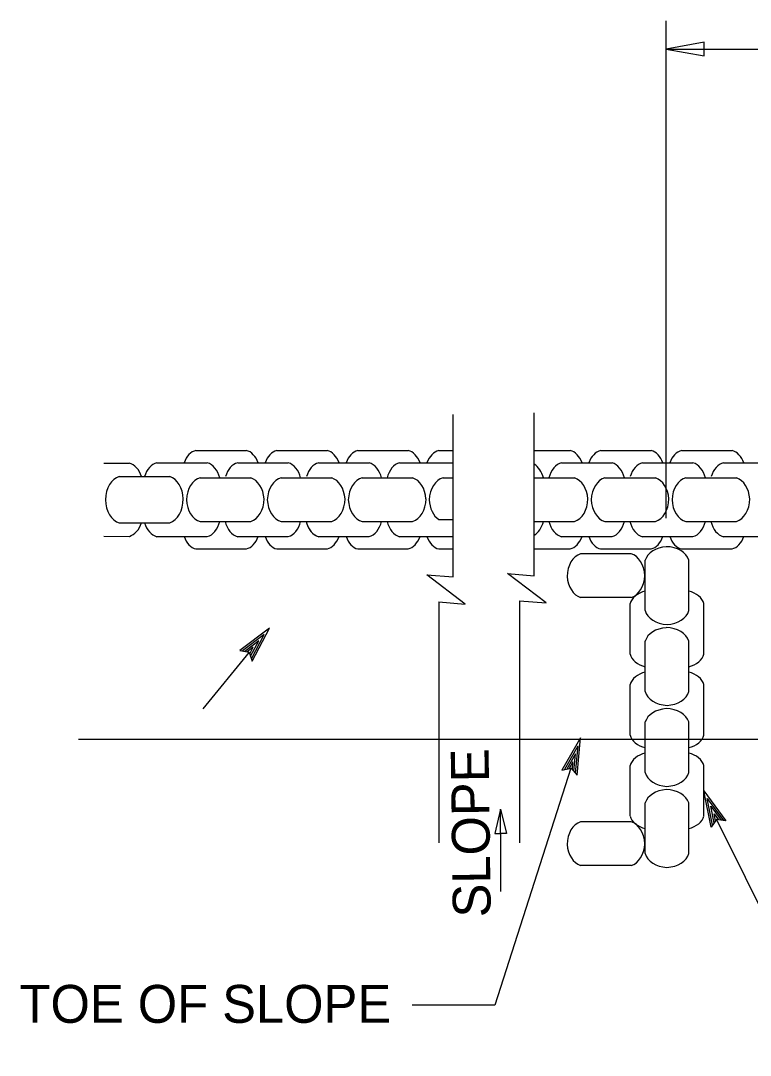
# Model space of a CAD drawing. Extents: x 6707406 to 6714471, y 1868570 to 1872341.
# Drawn here: x 6712391.8 to 6712507.4, y 1870300.6 to 1870464.4 of the extents above; entities that cross this region are included whole.
import ezdxf

# ---------------------------------------------------------------- set-up
doc = ezdxf.new("R2010")
doc.units = 0
for name, color, linetype in [('56 Stg 3 Anno', 7, 'Continuous'), ('C - SANDBAG', 7, 'Continuous'), ('Default', 7, 'Continuous'), ('G-SYMB', 7, 'Continuous'), ('G-TEXT', 7, 'Continuous')]:
    doc.layers.add(name, color=color, linetype=linetype)

# ---------------------------------------------------------------- blocks, each defined once
blk = doc.blocks.new('ARROW')
at = {"layer": 'Default'}
blk.add_lwpolyline([(-0.01042, -0.00183), (0, 0), (-0.01042, 0.00183)], close=True, dxfattribs=at)

msp = doc.modelspace()

# ---------------------------------------------------------------- linework, layer by layer
at = {"layer": '56 Stg 3 Anno'}
for p, q in [((6712431.26, 1870368.21), (6712426.55, 1870364.65)), ((6712428.5, 1870362.99), (6712431.26, 1870368.21)), ((6712431.26, 1870368.21), (6712431.26, 1870368.21)), ((6712430.39, 1870367.19), (6712426.96, 1870364.6)), ((6712428.37, 1870363.37), (6712430.4, 1870367.2)), ((6712426.55, 1870364.65), (6712426.55, 1870364.65)), ((6712426.55, 1870364.65), (6712428.02, 1870364.41)), ((6712429.54, 1870366.19), (6712427.32, 1870364.51)), ((6712428.68, 1870365.18), (6712427.73, 1870364.46)), ((6712428.11, 1870364.11), (6712428.68, 1870365.18)), ((6712428.26, 1870363.76), (6712429.54, 1870366.19)), ((6712428.02, 1870364.41), (6712428.5, 1870362.99)), ((6712428.5, 1870362.99), (6712428.5, 1870362.99)), ((6712480.51, 1870350.81), (6712477.55, 1870345.7)), ((6712480, 1870344.93), (6712480.51, 1870350.81)), ((6712480.51, 1870350.81), (6712480.51, 1870350.81)), ((6712480.1, 1870349.54), (6712477.95, 1870345.82)), ((6712479.71, 1870348.28), (6712478.32, 1870345.88)), ((6712479.47, 1870345.55), (6712479.71, 1870348.28)), ((6712479.73, 1870345.23), (6712480.11, 1870349.55)), ((6712479.31, 1870347.02), (6712478.71, 1870345.99)), ((6712479.21, 1870345.81), (6712479.31, 1870347.02)), ((6712477.55, 1870345.71), (6712479, 1870346.05)), ((6712477.55, 1870345.71), (6712477.55, 1870345.71)), ((6712479, 1870346.05), (6712480, 1870344.93)), ((6712480, 1870344.93), (6712480, 1870344.93)), ((6712501.2, 1870336.67), (6712500.05, 1870342.46)), ((6712500.05, 1870342.46), (6712500.05, 1870342.46)), ((6712500.05, 1870342.46), (6712503.54, 1870337.7)), ((6712501.42, 1870337), (6712500.58, 1870341.25)), ((6712500.59, 1870341.24), (6712503.14, 1870337.77)), ((6712501.65, 1870337.34), (6712501.12, 1870340.03)), ((6712501.12, 1870340.03), (6712502.76, 1870337.79)), ((6712501.89, 1870337.63), (6712501.65, 1870338.82)), ((6712501.65, 1870338.82), (6712502.36, 1870337.86)), ((6712502.06, 1870337.89), (6712501.2, 1870336.67)), ((6712503.54, 1870337.7), (6712502.06, 1870337.89)), ((6712503.54, 1870337.7), (6712503.54, 1870337.7)), ((6712501.2, 1870336.67), (6712501.2, 1870336.67))]:
    msp.add_line(p, q, dxfattribs=at)
at = {"layer": 'C - SANDBAG'}
for p, q in [((6712419.58, 1870396.35), (6712427.59, 1870396.35)), ((6712432.4, 1870396.35), (6712440.41, 1870396.35)), ((6712445.22, 1870396.35), (6712453.23, 1870396.35)), ((6712445.22, 1870396.35), (6712453.23, 1870396.35)), ((6712458.04, 1870396.35), (6712460.36, 1870396.35)), ((6712473.18, 1870396.35), (6712478.87, 1870396.35)), ((6712483.68, 1870396.35), (6712491.69, 1870396.35)), ((6712496.51, 1870396.35), (6712504.51, 1870396.35)), ((6712405, 1870394.34), (6712409.05, 1870394.35)), ((6712413.39, 1870394.4), (6712421.39, 1870394.4)), ((6712426.21, 1870394.39), (6712434.22, 1870394.39)), ((6712439.03, 1870394.39), (6712447.04, 1870394.39)), ((6712439.03, 1870394.39), (6712447.04, 1870394.39)), ((6712451.85, 1870394.39), (6712460.36, 1870394.39)), ((6712477.49, 1870394.39), (6712485.5, 1870394.39)), ((6712490.31, 1870394.39), (6712498.32, 1870394.39)), ((6712503.13, 1870394.39), (6712511.14, 1870394.39)), ((6712407.45, 1870392.19), (6712415.46, 1870392.19)), ((6712420.27, 1870391.99), (6712428.28, 1870391.99)), ((6712433.09, 1870391.99), (6712441.1, 1870391.99)), ((6712445.91, 1870391.99), (6712453.92, 1870391.99)), ((6712445.91, 1870391.99), (6712453.92, 1870391.99)), ((6712458.73, 1870391.99), (6712460.36, 1870391.99)), ((6712473.18, 1870391.99), (6712479.56, 1870391.99)), ((6712484.37, 1870391.99), (6712492.38, 1870391.99)), ((6712497.19, 1870391.99), (6712505.2, 1870391.99)), ((6712407.45, 1870384.89), (6712415.46, 1870384.89)), ((6712420.27, 1870385.1), (6712428.28, 1870385.1)), ((6712433.09, 1870385.1), (6712441.1, 1870385.1)), ((6712445.91, 1870385.1), (6712453.92, 1870385.1)), ((6712445.91, 1870385.1), (6712453.92, 1870385.1)), ((6712458.04, 1870385.41), (6712460.36, 1870385.41)), ((6712473.18, 1870385.1), (6712479.56, 1870385.1)), ((6712484.37, 1870385.1), (6712492.38, 1870385.1)), ((6712497.19, 1870385.1), (6712505.2, 1870385.1)), ((6712405, 1870382.75), (6712409.05, 1870382.74)), ((6712413.39, 1870382.69), (6712421.39, 1870382.69)), ((6712426.21, 1870382.69), (6712434.22, 1870382.69)), ((6712439.03, 1870382.69), (6712447.04, 1870382.69)), ((6712439.03, 1870382.69), (6712447.04, 1870382.69)), ((6712451.85, 1870382.69), (6712460.36, 1870382.69)), ((6712477.49, 1870382.69), (6712485.5, 1870382.69)), ((6712490.31, 1870382.69), (6712498.32, 1870382.69)), ((6712503.13, 1870382.69), (6712511.14, 1870382.69)), ((6712419.58, 1870380.74), (6712427.59, 1870380.74)), ((6712432.4, 1870380.74), (6712440.41, 1870380.74)), ((6712445.22, 1870380.74), (6712453.23, 1870380.74)), ((6712445.22, 1870380.74), (6712453.23, 1870380.74)), ((6712458.04, 1870380.74), (6712460.36, 1870380.74)), ((6712473.18, 1870380.74), (6712478.87, 1870380.74)), ((6712488.51, 1870379.96), (6712480.5, 1870379.96)), ((6712483.68, 1870380.74), (6712491.69, 1870380.74)), ((6712496.51, 1870380.74), (6712504.51, 1870380.74)), ((6712490.76, 1870370.98), (6712490.76, 1870378.99)), ((6712497.65, 1870370.98), (6712497.65, 1870378.99)), ((6712488.51, 1870373.07), (6712480.5, 1870373.07)), ((6712488.35, 1870364.1), (6712488.35, 1870372.1)), ((6712500.05, 1870364.1), (6712500.05, 1870372.1)), ((6712490.75, 1870358.16), (6712490.75, 1870366.17)), ((6712497.65, 1870358.16), (6712497.65, 1870366.17)), ((6712488.35, 1870351.28), (6712488.35, 1870359.28)), ((6712500.05, 1870351.28), (6712500.05, 1870359.28)), ((6712490.75, 1870345.34), (6712490.75, 1870353.35)), ((6712497.65, 1870345.34), (6712497.65, 1870353.35)), ((6712488.35, 1870338.46), (6712488.35, 1870346.46)), ((6712500.05, 1870338.46), (6712500.05, 1870346.46)), ((6712490.75, 1870332.52), (6712490.75, 1870340.52)), ((6712490.75, 1870332.52), (6712490.75, 1870340.52)), ((6712497.65, 1870332.52), (6712497.65, 1870340.52)), ((6712497.65, 1870332.52), (6712497.65, 1870340.52)), ((6712488.51, 1870337.53), (6712480.5, 1870337.53)), ((6712488.51, 1870330.63), (6712480.5, 1870330.63))]:
    msp.add_line(p, q, dxfattribs=at)
for centre, major_axis, ratio, start_param, end_param in [((6712420.11, 1870392.67), (0.06, -3.75), 0.711359, 3.317588, 4.221159), ((6712427.1, 1870392.67), (0.06, -3.75), 0.71077, 2.038051, 2.935943), ((6712432.93, 1870392.66), (0.06, -3.75), 0.711359, 3.317588, 4.221159), ((6712439.92, 1870392.67), (0.06, -3.75), 0.71077, 2.038051, 2.935943), ((6712445.75, 1870392.66), (0.06, -3.75), 0.711359, 3.317588, 4.221159), ((6712445.75, 1870392.66), (0.06, -3.75), 0.711359, 3.317588, 4.221159), ((6712452.74, 1870392.67), (0.06, -3.75), 0.71077, 2.038051, 2.935943), ((6712452.74, 1870392.67), (0.06, -3.75), 0.71077, 2.038051, 2.935943), ((6712458.57, 1870392.66), (0.06, -3.75), 0.711359, 3.317588, 4.221159), ((6712478.39, 1870392.67), (0.06, -3.75), 0.71077, 2.038051, 2.935943), ((6712484.21, 1870392.66), (0.06, -3.75), 0.711359, 3.317588, 4.221159), ((6712491.21, 1870392.66), (0.06, -3.75), 0.71077, 2.038051, 2.935943), ((6712497.03, 1870392.66), (0.06, -3.75), 0.711359, 3.317588, 4.221159), ((6712504.03, 1870392.66), (0.06, -3.75), 0.71077, 2.038051, 2.935943), ((6712408.56, 1870390.67), (0.06, -3.75), 0.71077, 1.978332, 2.935943), ((6712413.91, 1870390.71), (0.06, -3.75), 0.711359, 3.317588, 4.29466), ((6712420.85, 1870390.72), (0, -3.75), 0.71077, 1.915159, 2.935943), ((6712426.73, 1870390.71), (0.06, -3.75), 0.711359, 3.317588, 4.29466), ((6712433.67, 1870390.72), (0, -3.75), 0.71077, 1.915159, 2.935943), ((6712439.56, 1870390.71), (0.06, -3.75), 0.711359, 3.317588, 4.29466), ((6712439.56, 1870390.71), (0.06, -3.75), 0.711359, 3.317588, 4.29466), ((6712446.49, 1870390.72), (0, -3.75), 0.71077, 1.915159, 2.935943), ((6712446.49, 1870390.72), (0, -3.75), 0.71077, 1.915159, 2.935943), ((6712452.38, 1870390.71), (0.06, -3.75), 0.711359, 3.317588, 4.353284), ((6712472.13, 1870390.72), (0, -3.75), 0.71077, 1.915159, 2.738799), ((6712478.02, 1870390.71), (0.06, -3.75), 0.711359, 3.317588, 4.353284), ((6712484.95, 1870390.72), (0, -3.75), 0.71077, 1.915159, 2.935943), ((6712490.84, 1870390.71), (0.06, -3.75), 0.711359, 3.317588, 4.29466), ((6712497.77, 1870390.72), (0, -3.75), 0.71077, 1.915159, 2.935943), ((6712503.66, 1870390.71), (0.06, -3.75), 0.711359, 3.317588, 4.29466), ((6712407.92, 1870388.5), (0, -3.75), 0.711359, 3.317588, 4.701658), ((6712414.91, 1870388.52), (0, -3.75), 0.71077, 1.607523, 2.935943), ((6712420.74, 1870388.3), (0, -3.75), 0.711359, 3.317588, 4.646994), ((6712427.73, 1870388.32), (0, -3.75), 0.71077, 1.662213, 2.935943), ((6712433.56, 1870388.3), (0, -3.75), 0.711359, 3.317588, 4.646994), ((6712440.55, 1870388.32), (0, -3.75), 0.71077, 1.662213, 2.935943), ((6712446.38, 1870388.3), (0, -3.75), 0.711359, 3.317588, 4.646994), ((6712446.38, 1870388.3), (0, -3.75), 0.711359, 3.317588, 4.646994), ((6712453.37, 1870388.32), (0, -3.75), 0.71077, 1.662213, 2.935943), ((6712453.37, 1870388.32), (0, -3.75), 0.71077, 1.662213, 2.935943), ((6712459.2, 1870388.3), (0, -3.75), 0.711359, 3.317588, 4.646994), ((6712479.02, 1870388.31), (0, -3.75), 0.71077, 1.662213, 2.935943), ((6712484.84, 1870388.3), (0, -3.75), 0.711359, 3.317588, 4.646994), ((6712491.84, 1870388.31), (0, -3.75), 0.71077, 1.662213, 2.935943), ((6712497.66, 1870388.3), (0, -3.75), 0.711359, 3.317588, 4.646994), ((6712504.66, 1870388.31), (0, -3.75), 0.71077, 1.662213, 2.935943), ((6712407.92, 1870388.58), (0, 3.75), 0.711359, 1.581528, 2.965597), ((6712414.91, 1870388.57), (0, 3.75), 0.71077, 3.347242, 4.737291), ((6712420.74, 1870388.79), (0, 3.75), 0.711359, 1.636191, 2.965597), ((6712427.73, 1870388.77), (0, 3.75), 0.71077, 3.347242, 4.682592), ((6712433.56, 1870388.79), (0, 3.75), 0.711359, 1.636191, 2.965597), ((6712440.55, 1870388.77), (0, 3.75), 0.71077, 3.347242, 4.682592), ((6712446.38, 1870388.79), (0, 3.75), 0.711359, 1.636191, 2.965597), ((6712446.38, 1870388.79), (0, 3.75), 0.711359, 1.636191, 2.965597), ((6712453.37, 1870388.77), (0, 3.75), 0.71077, 3.347242, 4.682592), ((6712453.37, 1870388.77), (0, 3.75), 0.71077, 3.347242, 4.682592), ((6712459.2, 1870388.79), (0, 3.75), 0.711359, 1.636191, 2.692877), ((6712479.02, 1870388.77), (0, 3.75), 0.71077, 3.347242, 4.682592), ((6712484.84, 1870388.79), (0, 3.75), 0.711359, 1.636191, 2.965597), ((6712491.84, 1870388.77), (0, 3.75), 0.71077, 3.347242, 4.682592), ((6712497.66, 1870388.79), (0, 3.75), 0.711359, 1.636191, 2.965597), ((6712504.66, 1870388.77), (0, 3.75), 0.71077, 3.347242, 4.682592), ((6712408.56, 1870386.42), (0.06, 3.75), 0.71077, 3.347242, 4.304853), ((6712413.91, 1870386.37), (0.06, 3.75), 0.711359, 1.988526, 2.965597), ((6712420.85, 1870386.36), (0, 3.75), 0.71077, 3.347242, 4.368026), ((6712426.73, 1870386.37), (0.06, 3.75), 0.711359, 1.929645, 2.965597), ((6712433.67, 1870386.36), (0, 3.75), 0.71077, 3.347242, 4.368026), ((6712439.56, 1870386.37), (0.06, 3.75), 0.711359, 1.929645, 2.965597), ((6712439.56, 1870386.37), (0.06, 3.75), 0.711359, 1.988526, 2.965597), ((6712446.49, 1870386.36), (0, 3.75), 0.71077, 3.347242, 4.368026), ((6712446.49, 1870386.36), (0, 3.75), 0.71077, 3.347242, 4.368026), ((6712452.38, 1870386.37), (0.06, 3.75), 0.711359, 1.929645, 2.965597), ((6712472.13, 1870386.36), (0, 3.75), 0.71077, 3.544386, 4.368026), ((6712478.02, 1870386.37), (0.06, 3.75), 0.711359, 1.929645, 2.965597), ((6712484.95, 1870386.36), (0, 3.75), 0.71077, 3.347242, 4.368026), ((6712490.84, 1870386.37), (0.06, 3.75), 0.711359, 1.929645, 2.965597), ((6712497.77, 1870386.36), (0, 3.75), 0.71077, 3.347242, 4.368026), ((6712503.66, 1870386.37), (0.06, 3.75), 0.711359, 1.929645, 2.965597), ((6712420.11, 1870384.42), (0.06, 3.75), 0.711359, 2.062027, 2.965597), ((6712427.1, 1870384.42), (0.06, 3.75), 0.71077, 3.347242, 4.244863), ((6712432.93, 1870384.42), (0.06, 3.75), 0.711359, 2.062027, 2.965597), ((6712439.92, 1870384.42), (0.06, 3.75), 0.71077, 3.347242, 4.244863), ((6712445.75, 1870384.42), (0.06, 3.75), 0.711359, 2.062027, 2.965597), ((6712445.75, 1870384.42), (0.06, 3.75), 0.711359, 2.062027, 2.965597), ((6712452.74, 1870384.42), (0.06, 3.75), 0.71077, 3.347242, 4.244863), ((6712452.74, 1870384.42), (0.06, 3.75), 0.71077, 3.347242, 4.244863), ((6712458.57, 1870384.42), (0.06, 3.75), 0.711359, 2.062027, 2.965597), ((6712478.39, 1870384.42), (0.06, 3.75), 0.71077, 3.347242, 4.244863), ((6712484.21, 1870384.42), (0.06, 3.75), 0.711359, 2.062027, 2.965597), ((6712491.21, 1870384.42), (0.06, 3.75), 0.71077, 3.347242, 4.244863), ((6712497.03, 1870384.42), (0.06, 3.75), 0.711359, 2.062027, 2.965597), ((6712504.03, 1870384.42), (0.06, 3.75), 0.71077, 3.347242, 4.244863), ((6712494.43, 1870378.44), (3.75, 0), 0.71077, 1.662213, 2.935943), ((6712493.97, 1870378.44), (-3.75, 0), 0.71077, 3.347242, 4.682592), ((6712481.04, 1870376.28), (0, -3.75), 0.71077, 3.347242, 4.682592), ((6712488.04, 1870376.27), (0, -3.75), 0.711359, 1.636191, 2.965597), ((6712481.04, 1870376.74), (0, 3.75), 0.71077, 1.662213, 2.935943), ((6712488.04, 1870376.76), (0, 3.75), 0.711359, 3.317588, 4.646994), ((6712492.02, 1870371.56), (3.75, 0), 0.71077, 1.915159, 2.935943), ((6712496.38, 1870371.56), (-3.75, 0), 0.71077, 3.347242, 4.368026), ((6712494.45, 1870371.45), (3.75, 0), 0.711359, 3.317588, 4.646994), ((6712493.96, 1870371.45), (-3.75, 0), 0.711359, 1.636191, 2.965597), ((6712494.43, 1870365.62), (3.75, 0), 0.71077, 1.662213, 2.935943), ((6712493.97, 1870365.62), (-3.75, 0), 0.71077, 3.347242, 4.682592), ((6712492.03, 1870364.62), (3.75, 0.06), 0.711359, 3.317588, 4.353284), ((6712496.37, 1870364.62), (-3.75, 0.06), 0.711359, 1.929645, 2.965597), ((6712492.02, 1870358.74), (3.75, 0), 0.71077, 1.915159, 2.935943), ((6712496.38, 1870358.74), (-3.75, 0), 0.71077, 3.347242, 4.368026), ((6712494.45, 1870358.63), (3.75, 0), 0.711359, 3.317588, 4.646994), ((6712493.96, 1870358.63), (-3.75, 0), 0.711359, 1.636191, 2.965597), ((6712494.43, 1870352.8), (3.75, 0), 0.71077, 1.662213, 2.935943), ((6712493.97, 1870352.8), (-3.75, 0), 0.71077, 3.347242, 4.682592), ((6712492.03, 1870351.8), (3.75, 0.06), 0.711359, 3.317588, 4.353284), ((6712496.37, 1870351.8), (-3.75, 0.06), 0.711359, 1.929645, 2.965597), ((6712492.02, 1870345.92), (3.75, 0), 0.71077, 1.915159, 2.935943), ((6712496.38, 1870345.92), (-3.75, 0), 0.71077, 3.347242, 4.368026), ((6712494.44, 1870345.81), (3.75, 0), 0.711359, 3.317588, 4.646994), ((6712493.95, 1870345.81), (-3.75, 0), 0.711359, 1.636191, 2.965597), ((6712494.43, 1870339.98), (3.75, 0), 0.71077, 1.662213, 2.935943), ((6712494.43, 1870339.98), (3.75, 0), 0.71077, 1.662213, 2.935943), ((6712493.97, 1870339.98), (-3.75, 0), 0.71077, 3.347242, 4.682592), ((6712493.97, 1870339.98), (-3.75, 0), 0.71077, 3.347242, 4.682592), ((6712492.03, 1870338.98), (3.75, 0.06), 0.711359, 3.317588, 4.353284), ((6712496.37, 1870338.98), (-3.75, 0.06), 0.711359, 1.929645, 2.965597), ((6712481.04, 1870333.85), (0, -3.75), 0.71077, 3.347242, 4.682592), ((6712488.04, 1870333.83), (0, -3.75), 0.711359, 1.636191, 2.965597), ((6712481.04, 1870334.31), (0, 3.75), 0.71077, 1.662213, 2.935943), ((6712488.04, 1870334.32), (0, 3.75), 0.711359, 3.317588, 4.646994), ((6712494.44, 1870332.98), (3.75, 0), 0.711359, 3.317588, 4.646994), ((6712493.95, 1870332.98), (-3.75, 0), 0.711359, 1.636191, 2.965597)]:
    msp.add_ellipse(centre, major_axis=major_axis, ratio=ratio, start_param=start_param, end_param=end_param, dxfattribs=at)
at = {"layer": 'G-SYMB'}
for p, q in [((6712494.09, 1870385.6), (6712494.09, 1870464.39)), ((6712494.09, 1870459.89), (6712622.31, 1870459.89)), ((6712460.36, 1870376.31), (6712460.36, 1870402.01)), ((6712473.18, 1870376.49), (6712473.18, 1870402.29)), ((6712460.36, 1870376.31), (6712460.36, 1870376.31)), ((6712473.18, 1870376.49), (6712473.18, 1870376.49)), ((6712458.04, 1870372.37), (6712458.04, 1870372.37)), ((6712458.04, 1870372.37), (6712458.04, 1870334.23)), ((6712470.86, 1870372.55), (6712470.86, 1870372.55)), ((6712470.86, 1870372.55), (6712470.86, 1870334.23)), ((6712428.03, 1870364.41), (6712420.69, 1870355.44)), ((6712401.02, 1870350.62), (6712788.96, 1870350.62)), ((6712467.85, 1870335.71), (6712467.85, 1870326.52)), ((6712467.85, 1870335.71), (6712467.85, 1870326.52))]:
    msp.add_line(p, q, dxfattribs=at)
for points in [[(6712458.04, 1870372.37), (6712462.26, 1870372.01), (6712456.14, 1870376.66), (6712460.36, 1870376.31)], [(6712470.86, 1870372.55), (6712475.08, 1870372.19), (6712468.96, 1870376.84), (6712473.18, 1870376.49)]]:
    msp.add_lwpolyline(points, dxfattribs=at)
for points in [[(6712472.02, 1870374.52), (6712472.02, 1870374.52)], [(6712459.2, 1870374.34), (6712459.2, 1870374.34)], [(6712466.94, 1870335.69), (6712467.85, 1870335.69), (6712467.85, 1870339.54)], [(6712468.76, 1870335.69), (6712467.85, 1870335.69), (6712467.85, 1870339.54)]]:
    msp.add_lwpolyline(points, close=True, dxfattribs=at)
at = {"layer": 'G-TEXT'}
for p, q in [((6712478.98, 1870346.03), (6712466.95, 1870308.49)), ((6712502.06, 1870337.89), (6712520.56, 1870300.57)), ((6712466.95, 1870308.49), (6712453.84, 1870308.49))]:
    msp.add_line(p, q, dxfattribs=at)

# ---------------------------------------------------------------- block references
at = {"layer": 'G-SYMB', "xscale": 575.9999999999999, "yscale": 589.090909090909, "rotation": 180}
msp.add_blockref('ARROW', (6712494.09, 1870459.89), dxfattribs=at)

# ---------------------------------------------------------------- texts
at = {"layer": 'G-TEXT'}
for s, rotation, p in [('SLOPE', 90.764, (6712466.3, 1870322.43)), ('TOE OF SLOPE', 360, (6712391.66, 1870305.71))]:
    msp.add_text(s, height=6, rotation=rotation, dxfattribs=at).set_placement(p)

doc.saveas('drawing.dxf')
